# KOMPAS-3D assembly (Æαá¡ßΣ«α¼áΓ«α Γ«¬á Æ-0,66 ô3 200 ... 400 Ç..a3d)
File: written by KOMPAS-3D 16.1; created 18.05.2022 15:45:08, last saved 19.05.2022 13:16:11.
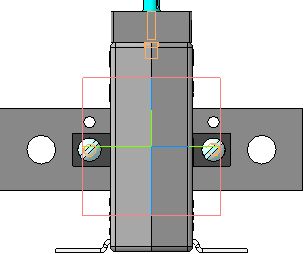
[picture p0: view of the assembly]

Referenced files in D:\Трансформаторы Т-0,66\МОДЕЛИ\: ИКП.Э.101.300.002 Полукорпус Л2.m3d, ИКП.Э.101.300.001 Полукорпус Л1.m3d, ИКП.Э.101.100.013 Контакт вторичный.m3d, Винт М5-6-Z.m3d, ИКП.Э.101.100.003 Ножка.m3d, Саморез 3-16.m3d, Оттиск поверителя.m3d, ИКП.Э.101.300.005 Планка.m3d, ИКП.Э.101.300.007 Шина алюминиевая.m3d, ИКП.Э.101.300.004 Крышка.m3d, Винт пломбировочный М4-10.m3d, Винт М5-20.m3d
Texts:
  pc-21
  (ф) ИКП.Э.101.300.002 Полукорпус Л2
  (+) ИКП.Э.101.300.001 Полукорпус Л1
  (+) ИКП.Э.101.100.013 Контакт вторичный (1)
  (+) ИКП.Э.101.100.013 Контакт вторичный (2)
  (+) Винт М5-6-Z (1)
  (+) Винт М5-6-Z (2)
  (+) ИКП.Э.101.100.003 Ножка (1)
  (+) ИКП.Э.101.100.003 Ножка (2)
  (+) ИКП.Э.101.100.003 Ножка (3)
  (+) ИКП.Э.101.100.003 Ножка (4)
  (-) Саморез 3-16 (1)
  (-) Саморез 3-16 (2)
  (-) Саморез 3-16 (3)
  (-) Саморез 3-16 (4)
  (+) Оттиск поверителя
  (+) ИКП.Э.101.300.005 Планка
  (+) ИКП.Э.101.300.004 Крышка
  (+) Винт пломбировочный М4-30
  (+) Винт М5-20 (1)
  (+) Винт М5-20 (2)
